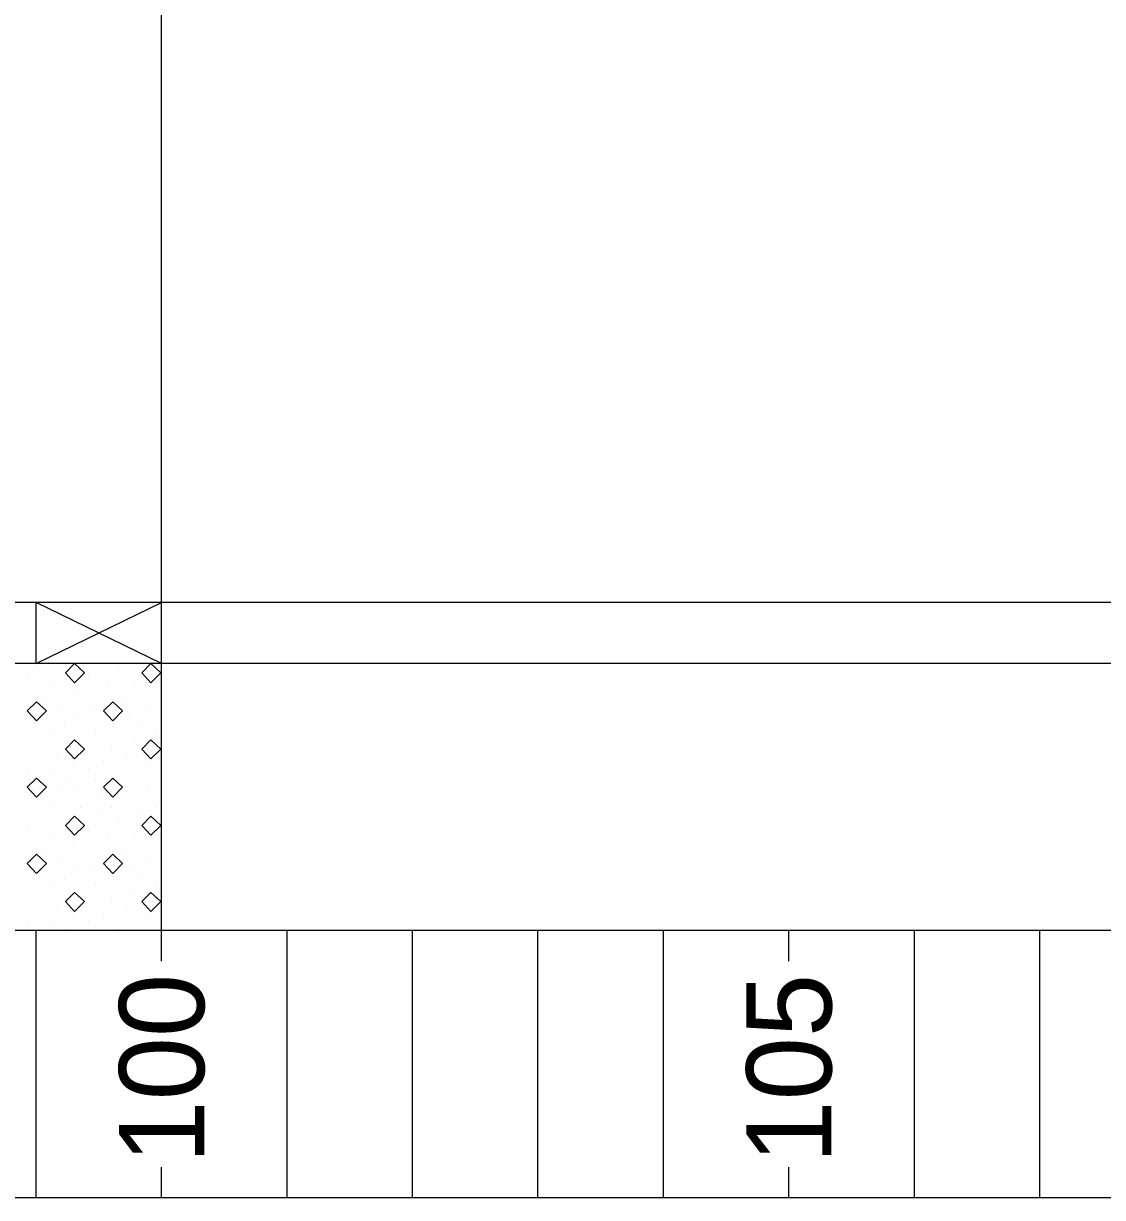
# Model space of a CAD drawing. Extents: x 1313964 to 1316843, y 2087046 to 2096619.
# Drawn here: x 1314098.19 to 1314106.79, y 2089928.16 to 2089937.53 of the extents above; entities that cross this region are included whole.
import ezdxf

# ---------------------------------------------------------------- set-up
doc = ezdxf.new("R2010")
doc.units = 0
doc.layers.add('B-Sub-Contour', color=7, linetype='Continuous')
doc.layers.add('Default', color=7, linetype='Continuous')

# ---------------------------------------------------------------- blocks, each defined once
blk = doc.blocks.new('POINT_DISPLAY')
at = {"layer": 'Default'}
blk.add_line((0, 0), (0, 0), dxfattribs=at)

msp = doc.modelspace()

# ---------------------------------------------------------------- linework, layer by layer
at = {"layer": 'B-Sub-Contour'}
for points in [[(1314136.7248, 2089928.1639), (1314136.7248, 2089971.0354), (1314075.306, 2089971.0354), (1314075.306, 2089928.1639), (1314136.7248, 2089928.1639)], [(1314099.2924, 2089932.9071), (1314099.2924, 2089948.7787)], [(1314134.2924, 2089932.9071), (1314089.2925, 2089932.9071)], [(1314098.2924, 2089932.4207), (1314099.2924, 2089932.9071)], [(1314099.2924, 2089932.4207), (1314098.2924, 2089932.9071)], [(1314098.2924, 2089932.4207), (1314098.2924, 2089932.9071)], [(1314099.2924, 2089932.4207), (1314099.2924, 2089932.9071)], [(1314099.2924, 2089932.4207), (1314099.2924, 2089932.9071)], [(1314134.2924, 2089932.4207), (1314082.6033, 2089932.4207)], [(1314099.2924, 2089930.2923), (1314099.2924, 2089932.4207)], [(1314134.2924, 2089930.2923), (1314082.6033, 2089930.2923)], [(1314098.2924, 2089928.1639), (1314098.2924, 2089930.2923)], [(1314099.2924, 2089930.049), (1314099.2924, 2089930.2923)], [(1314099.2924, 2089930.049), (1314099.2924, 2089930.2923)], [(1314100.2924, 2089928.1639), (1314100.2924, 2089930.2923)], [(1314101.2924, 2089928.1639), (1314101.2924, 2089930.2923)], [(1314101.2924, 2089928.1639), (1314101.2924, 2089930.2923)], [(1314102.2924, 2089928.1639), (1314102.2924, 2089930.2923)], [(1314103.2924, 2089928.1639), (1314103.2924, 2089930.2923)], [(1314103.2924, 2089928.1639), (1314103.2924, 2089930.2923)], [(1314104.2924, 2089930.049), (1314104.2924, 2089930.2923)], [(1314105.2924, 2089928.1639), (1314105.2924, 2089930.2923)], [(1314105.2924, 2089928.1639), (1314105.2924, 2089930.2923)], [(1314106.2924, 2089928.1639), (1314106.2924, 2089930.2923)], [(1314099.2924, 2089928.1639), (1314099.2924, 2089928.4071)], [(1314099.2924, 2089928.1639), (1314099.2924, 2089928.4071)], [(1314104.2924, 2089928.1639), (1314104.2924, 2089928.4071)]]:
    msp.add_lwpolyline(points, dxfattribs=at)
for points in [[(1314098.5985, 2089932.4207), (1314098.5255, 2089932.3477), (1314098.5985, 2089932.2686), (1314098.6776, 2089932.3477)], [(1314099.2066, 2089932.4207), (1314099.1337, 2089932.3477), (1314099.2066, 2089932.2686), (1314099.2857, 2089932.3477)], [(1314098.2945, 2089932.1166), (1314098.2215, 2089932.0436), (1314098.2945, 2089931.9646), (1314098.3735, 2089932.0436)], [(1314098.9026, 2089932.1166), (1314098.8296, 2089932.0436), (1314098.9026, 2089931.9646), (1314098.9816, 2089932.0436)], [(1314098.5985, 2089931.8125), (1314098.5255, 2089931.7396), (1314098.5985, 2089931.6605), (1314098.6776, 2089931.7396)], [(1314099.2066, 2089931.8125), (1314099.1337, 2089931.7396), (1314099.2066, 2089931.6605), (1314099.2857, 2089931.7396)], [(1314098.2945, 2089931.5085), (1314098.2215, 2089931.4355), (1314098.2945, 2089931.3565), (1314098.3735, 2089931.4355)], [(1314098.9026, 2089931.5085), (1314098.8296, 2089931.4355), (1314098.9026, 2089931.3565), (1314098.9816, 2089931.4355)], [(1314098.5985, 2089931.2044), (1314098.5255, 2089931.1315), (1314098.5985, 2089931.0524), (1314098.6776, 2089931.1315)], [(1314099.2066, 2089931.2044), (1314099.1337, 2089931.1315), (1314099.2066, 2089931.0524), (1314099.2857, 2089931.1315)], [(1314098.2945, 2089930.9004), (1314098.2215, 2089930.8274), (1314098.2945, 2089930.7484), (1314098.3735, 2089930.8274)], [(1314098.9026, 2089930.9004), (1314098.8296, 2089930.8274), (1314098.9026, 2089930.7484), (1314098.9816, 2089930.8274)], [(1314098.5985, 2089930.5963), (1314098.5255, 2089930.5234), (1314098.5985, 2089930.4443), (1314098.6776, 2089930.5234)], [(1314099.2066, 2089930.5963), (1314099.1337, 2089930.5234), (1314099.2066, 2089930.4443), (1314099.2857, 2089930.5234)]]:
    msp.add_lwpolyline(points, close=True, dxfattribs=at)

# ---------------------------------------------------------------- block references
at = {"layer": 'B-Sub-Contour', "xscale": 0.019951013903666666, "yscale": 0.019951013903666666, "rotation": 90}
for p in [(1314098.5255, 2089932.3705), (1314098.9512, 2089932.3705), (1314098.2215, 2089932.3097), (1314098.4343, 2089932.2848), (1314098.708, 2089932.3097), (1314098.8628, 2089932.282), (1314099.0728, 2089932.2489), (1314099.1945, 2089932.3097), (1314098.5864, 2089932.1881), (1314098.3431, 2089932.1272), (1314098.4647, 2089932.0664), (1314098.7246, 2089932.0363), (1314098.8296, 2089932.0664), (1314099.012, 2089932.1272), (1314099.1945, 2089932.0888), (1314098.2823, 2089931.9448), (1314098.5864, 2089932.0056), (1314099.0369, 2089932.0115), (1314099.1337, 2089931.9448), (1314098.4039, 2089931.884), (1314098.52, 2089931.9258), (1314098.7688, 2089931.884), (1314098.9098, 2089931.9176), (1314099.2553, 2089931.884), (1314098.6472, 2089931.7624), (1314098.8904, 2089931.7624), (1314099.0728, 2089931.8232), (1314098.4647, 2089931.7016), (1314099.012, 2089931.7016), (1314098.2215, 2089931.5799), (1314098.4039, 2089931.5799), (1314098.5864, 2089931.6408), (1314098.708, 2089931.5799), (1314098.8296, 2089931.6408), (1314099.1945, 2089931.6408), (1314098.2823, 2089931.5055), (1314098.5255, 2089931.5191), (1314098.7688, 2089931.4978), (1314098.9512, 2089931.5191), (1314098.4647, 2089931.4583), (1314098.5864, 2089931.3975), (1314098.8904, 2089931.4583), (1314099.012, 2089931.3975), (1314099.1806, 2089931.4415), (1314098.3431, 2089931.3367), (1314098.7854, 2089931.378), (1314098.4039, 2089931.2759), (1314098.6472, 2089931.2759), (1314098.7771, 2089931.2315), (1314098.8904, 2089931.2759), (1314099.1337, 2089931.2151), (1314099.2553, 2089931.2759), (1314098.5255, 2089931.1543), (1314098.9512, 2089931.1543), (1314098.2215, 2089931.0935), (1314098.4343, 2089931.0686), (1314098.708, 2089931.0935), (1314098.8628, 2089931.0658), (1314099.0728, 2089931.0326), (1314099.1945, 2089931.0935), (1314098.5864, 2089930.9718), (1314098.3431, 2089930.911), (1314098.4647, 2089930.8502), (1314098.7246, 2089930.8201), (1314098.8296, 2089930.8502), (1314099.012, 2089930.911), (1314099.1945, 2089930.8726), (1314098.2823, 2089930.7286), (1314098.5864, 2089930.7894), (1314099.0369, 2089930.7952), (1314099.1337, 2089930.7286), (1314098.4039, 2089930.6678), (1314098.52, 2089930.7096), (1314098.7688, 2089930.6678), (1314098.9098, 2089930.7013), (1314099.2553, 2089930.6678), (1314098.6472, 2089930.5462), (1314098.8904, 2089930.5462), (1314099.0728, 2089930.607), (1314098.4647, 2089930.4854), (1314099.012, 2089930.4854), (1314098.2215, 2089930.3637), (1314098.4039, 2089930.3637), (1314098.5864, 2089930.4245), (1314098.708, 2089930.3637), (1314098.8296, 2089930.4245), (1314099.1945, 2089930.4245), (1314098.5255, 2089930.3029), (1314098.9512, 2089930.3029)]:
    msp.add_blockref('POINT_DISPLAY', p, dxfattribs=at)

# ---------------------------------------------------------------- texts
at = {"layer": 'B-Sub-Contour'}
for s, p in [('100', (1314099.6318, 2089928.4341)), ('100', (1314099.6318, 2089928.4341)), ('105', (1314104.6317, 2089928.4341))]:
    msp.add_text(s, height=0.67865, rotation=90, dxfattribs=at).set_placement(p)

doc.saveas('drawing.dxf')
